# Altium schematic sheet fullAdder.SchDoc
size B
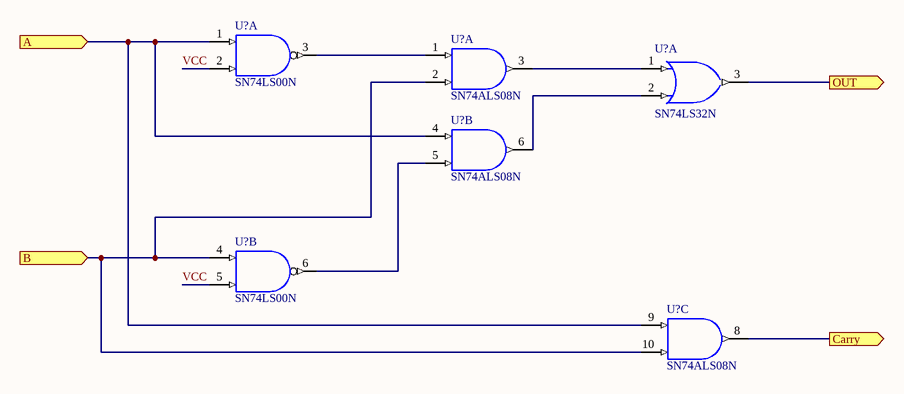
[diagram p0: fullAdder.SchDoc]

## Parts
(Parts that share a designator on the sheet are numbered #1, #2 ... from top to bottom, then left to right.)
U?#1  SN74LS00N  [DIP-14/D19.7]  (part A of 4)
U?#2  SN74ALS08N  [DIP-14/D19.7]  (part A of 4)
U?#3  SN74LS32N  [DIP-14/D19.7]  (part A of 4)
U?#4  SN74ALS08N  [DIP-14/D19.7]  (part B of 4)
U?#5  SN74LS00N  [DIP-14/D19.7]  (part B of 4)
U?#6  SN74ALS08N  [DIP-14/D19.7]  (part C of 4)

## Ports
A (in), B (in), Carry (out), OUT (out)

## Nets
GND: U?#1.7(GND) U?#2.7(GND) U?#3.7(GND) U?#4.7(GND) U?#5.7(GND) U?#6.7(GND)
VCC: U?#1.2(B) U?#1.14(VCC) U?#2.14(VCC) U?#3.14(VCC) U?#4.14(VCC) U?#5.5(B) U?#5.14(VCC) U?#6.14(VCC)
A: U?#1.1(A) U?#4.4(A) U?#6.9(A) ; port A
B: U?#2.2(B) U?#5.4(A) U?#6.10(B) ; port B
Carry: U?#6.8(Y) ; port Carry
OUT: U?#3.3(Y) ; port OUT
NetU?#1_3: U?#1.3(Y) U?#2.1(A)
NetU?#2_3: U?#2.3(Y) U?#3.1(A)
NetU?#3_2: U?#3.2(B) U?#4.6(Y)
NetU?#4_5: U?#4.5(B) U?#5.6(Y)

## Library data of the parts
U?#1 U?#5 = SN74LS00N: Quadruple 2-Input Positive-NAND Gate; Manufacturer: Texas Instruments; Class I: Logic
U?#2 U?#4 U?#6 = SN74ALS08N: Quadruple 2-Input Positive-AND Gate; Manufacturer: Texas Instruments; Class I: Logic
U?#3 = SN74LS32N: Quadruple 2-Input Positive-OR Gate; Manufacturer: Texas Instruments; Class I: Logic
